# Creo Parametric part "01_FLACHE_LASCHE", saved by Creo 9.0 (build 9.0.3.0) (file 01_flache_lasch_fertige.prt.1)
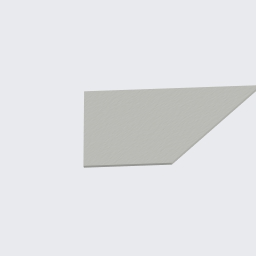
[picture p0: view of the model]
Materials in the file: S235JRG2

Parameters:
  BENENNUNG = "XXX"
  DATUM = "XX.XX.XX"
  ERSTELLER = "ARINDA"
  TEILETYP = "Fertigungsteil"
  SELECT_EN_NAME = "S235JRG2"
  SELECT_DIN_NAME = "RSt37-2"
  SELECT_DIN_NUMBER = "1.0038"
  SELECT_ASTM_NAME = "A 283 M Grade 2"
  MATERIAL_GROUP = "ME_ST_Baustahl"
  STANDARD_EN_DELIVERYSPEC = "DIN EN 10025"
  STANDARD_DIN_DELIVERYSPEC = "DIN 17100"

Other parameters: D10, D12, D13, D14, D15, D16, D17, D18, D19, D20, D22, D25, D30, D31, D43, SMT_PART_BEND_ALLOWANCE_FACTOR, SMT_DFLT_BEND_RADIUS, SMT_DFLT_BEND_ANGLE, SMT_DFLT_CRNR_REL_WIDTH, SMT_DFLT_CRNR_REL_DEPTH, SMT_DFLT_BEND_REL_WIDTH, SMT_DFLT_BEND_REL_DEPTH, SMT_DFLT_BEND_REL_ANGLE, SMT_GAP, SMT_DFLT_EDGE_TREA_WIDTH, SMT_DFLT_MITER_CUT_WIDTH, SMT_DFLT_MITER_CUT_OFFSET, MASSE, SMT_DFLT_BEND_REL_LENGTH

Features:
  1. coordinate system
  2. datum plane "DTM1", "T_RECHTS_Y-Z"
  3. datum plane "DTM2", "T_OBEN_X-Z"
  4. datum plane "DTM3", "T_VORNE_X-Y"
  5. datum axis "A_1"
  6. datum axis "A_2"
  7. datum axis "A_3"
  8. fill "Planar 1(Erste Lasche)"

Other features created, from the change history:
  feature "Flange 1"

Other named items: T_BASIS, A_X-ACHSE, A_Y-ACHSE, A_Z-ACHSE

Layers: 00_STD-ACHSEN, 00_STD-EBENEN, 00_STD-KOORDSYS, KURVENELEMENTE, SAMMELFLÄCHEN, VOLUMENGEOMETRIE

Surfaces: 6 plane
